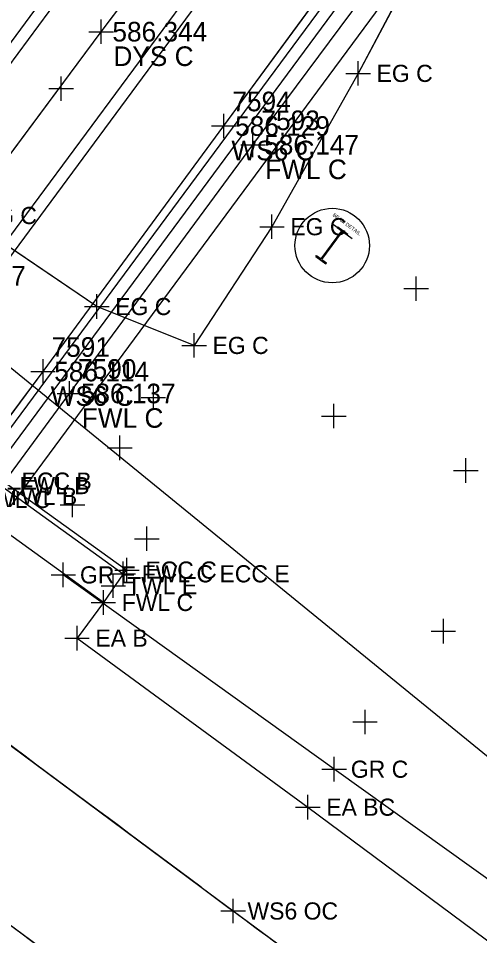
# Model space of a CAD drawing. Extents: x 1324236 to 1326110, y 459090 to 460782.
# Drawn here: x 1325190.8 to 1325228.5, y 460064.8 to 460139.7 of the extents above; entities that cross this region are included whole.
import ezdxf

# ---------------------------------------------------------------- set-up
doc = ezdxf.new("R2010")
doc.units = 0
for name, color, linetype in [('BD_X_Building', 7, 'Continuous'), ('BD_X_Canopy', 7, 'Continuous'), ('DR_X_Ditch', 7, 'Continuous'), ('DR_X_Storm_Sewer', 7, 'Continuous'), ('DT_X_Contour_Text', 7, 'Continuous'), ('DT_X_Terrain_Boundary', 7, 'Continuous'), ('DV_X_Property_Line', 7, 'Continuous'), ('E-RW-ODOT', 7, 'Continuous'), ('LT_X_Poles', 7, 'Continuous'), ('PM_X_Edge_Line', 7, 'Continuous'), ('PM_X_Lane_Line', 7, 'Continuous'), ('PM_X_Misc', 7, 'Continuous'), ('PV_X_Shoulder', 7, 'Continuous'), ('RW_X_CL', 7, 'Continuous'), ('RW_X_Esmt_SH', 7, 'Continuous'), ('UT_X_Gas', 7, 'Continuous')]:
    doc.layers.add(name, color=color, linetype=linetype)

msp = doc.modelspace()

# ---------------------------------------------------------------- linework, layer by layer
at = {"layer": 'BD_X_Building'}
for p, q in [((1325059.964, 459961.355), (1325206.222, 460159.32)), ((1325060.768, 459960.761), (1325207.027, 460158.725)), ((1325067.482, 459955.828), (1325213.75, 460153.784)), ((1325068.286, 459955.234), (1325214.554, 460153.19)), ((1325074.995, 459950.304), (1325221.27, 460148.255)), ((1325075.8, 459949.71), (1325222.074, 460147.66)), ((1325216.852, 460122.579), (1325216.9, 460122.643)), ((1325216.852, 460122.579), (1325217.222, 460122.305)), ((1325216.9, 460122.643), (1325217.704, 460122.049)), ((1325215.535, 460120.021), (1325217.222, 460122.305)), ((1325215.599, 460119.973), (1325217.286, 460122.258)), ((1325217.286, 460122.258), (1325217.656, 460121.984)), ((1325217.656, 460121.984), (1325217.704, 460122.049)), ((1325215.117, 460120.23), (1325215.165, 460120.294)), ((1325215.165, 460120.294), (1325215.535, 460120.021)), ((1325215.117, 460120.23), (1325215.921, 460119.636)), ((1325215.599, 460119.973), (1325215.969, 460119.7)), ((1325215.921, 460119.636), (1325215.969, 460119.7))]:
    msp.add_line(p, q, dxfattribs=at)
msp.add_circle((1325216.443, 460121.116), 3.038, dxfattribs=at)
at = {"layer": 'BD_X_Canopy'}
for points in [[(1325045.611, 459932.876), (1325057.851, 459949.53), (1325064.246, 459958.184), (1325079.335, 459978.633), (1325094.378, 459999.012), (1325110.069, 460020.457), (1325125.333, 460040.949), (1325138.348, 460058.621), (1325153.722, 460079.38), (1325168.359, 460099.091), (1325182.797, 460118.646), (1325197.597, 460138.568), (1325210.747, 460156.012)], [(1325148.737, 460096.817), (1325164.239, 460084.921), (1325164.239, 460084.921), (1325170.939, 460079.893), (1325170.939, 460079.893), (1325200.178, 460058.291), (1325200.178, 460058.291), (1325201.195, 460057.542), (1325201.195, 460057.542), (1325216.328, 460046.448), (1325216.328, 460046.448), (1325227.38, 460038.385), (1325227.38, 460038.385), (1325239.571, 460029.695)]]:
    msp.add_lwpolyline(points, dxfattribs=at)
at = {"layer": 'DR_X_Ditch'}
for points in [[(1325223.493, 460144.483), (1325218.56, 460135.167), (1325211.528, 460122.655), (1325205.182, 460112.968), (1325197.243, 460116.141), (1325186.279, 460123.568), (1325170.666, 460135.994), (1325176.384, 460144.867), (1325182.618, 460152.249), (1325187.649, 460158.581), (1325195.24, 460165.351)], [(1325155.492, 460106.108), (1325171.599, 460094.152), (1325171.599, 460094.152), (1325178.717, 460088.863), (1325178.717, 460088.863), (1325205.765, 460068.751), (1325205.765, 460068.751), (1325208.368, 460066.816), (1325208.368, 460066.816), (1325223.44, 460055.677), (1325223.44, 460055.677), (1325234.507, 460047.596)]]:
    msp.add_lwpolyline(points, dxfattribs=at)
at = {"layer": 'DR_X_Storm_Sewer'}
for p, q in [((1325197.597, 460138.568), (1325210.747, 460156.012)), ((1325182.797, 460118.646), (1325197.597, 460138.568))]:
    msp.add_line(p, q, dxfattribs=at)
at = {"layer": 'DT_X_Contour_Text'}
for p, q in [((1325209.977, 460129.336), (1325223.026, 460146.916)), ((1325223.493, 460144.483), (1325218.56, 460135.167)), ((1325218.56, 460135.167), (1325211.528, 460122.655)), ((1325195.021, 460109.046), (1325209.977, 460129.336)), ((1325197.243, 460116.141), (1325186.279, 460123.568)), ((1325211.528, 460122.655), (1325205.182, 460112.968)), ((1325205.182, 460112.968), (1325197.243, 460116.141)), ((1325180.628, 460089.515), (1325195.021, 460109.046))]:
    msp.add_line(p, q, dxfattribs=at)
at = {"layer": 'DT_X_Terrain_Boundary'}
for p, q in [((1325189.427, 460101.528), (1325199.405, 460094.329)), ((1325197.777, 460091.994), (1325186.129, 460100.396)), ((1325199.405, 460094.329), (1325197.777, 460091.994))]:
    msp.add_line(p, q, dxfattribs=at)
at = {"layer": 'DV_X_Property_Line'}
for p, q in [((1325218.56, 460134.167), (1325218.56, 460136.167)), ((1325217.56, 460135.167), (1325219.56, 460135.167)), ((1325209.977, 460128.336), (1325209.977, 460130.336)), ((1325208.977, 460129.336), (1325210.977, 460129.336)), ((1325211.528, 460121.655), (1325211.528, 460123.655)), ((1325210.528, 460122.655), (1325212.528, 460122.655)), ((1325197.243, 460115.141), (1325197.243, 460117.141)), ((1325196.243, 460116.141), (1325198.243, 460116.141)), ((1325205.182, 460111.968), (1325205.182, 460113.968)), ((1325204.182, 460112.968), (1325206.182, 460112.968)), ((1325195.021, 460108.046), (1325195.021, 460110.046)), ((1325194.021, 460109.046), (1325196.021, 460109.046)), ((1325199.701, 460093.634), (1325199.701, 460095.634)), ((1325199.405, 460093.329), (1325199.405, 460095.329)), ((1325198.405, 460094.329), (1325200.405, 460094.329)), ((1325198.59, 460092.361), (1325198.59, 460094.361)), ((1325198.701, 460094.634), (1325200.701, 460094.634)), ((1325197.59, 460093.361), (1325199.59, 460093.361)), ((1325197.777, 460090.994), (1325197.777, 460092.994)), ((1325196.777, 460091.994), (1325198.777, 460091.994)), ((1325195.63, 460088.08), (1325195.63, 460090.08)), ((1325194.63, 460089.08), (1325196.63, 460089.08)), ((1325214.459, 460074.287), (1325214.459, 460076.287)), ((1325213.459, 460075.287), (1325215.459, 460075.287))]:
    msp.add_line(p, q, dxfattribs=at)
at = {"layer": 'E-RW-ODOT'}
msp.add_line((1325273.546, 460043.161), (1325084.273, 460197.503), dxfattribs=at)
at = {"layer": 'LT_X_Poles'}
msp.add_lwpolyline([(1325155.492, 460106.108), (1325171.599, 460094.152), (1325171.599, 460094.152), (1325178.717, 460088.863), (1325178.717, 460088.863), (1325205.765, 460068.751), (1325205.765, 460068.751), (1325208.368, 460066.816), (1325208.368, 460066.816), (1325223.44, 460055.677), (1325223.44, 460055.677), (1325234.507, 460047.596)], dxfattribs=at)
at = {"layer": 'PM_X_Edge_Line'}
for p, q in [((1325207.605, 460130.872), (1325220.672, 460148.677)), ((1325192.857, 460110.836), (1325207.605, 460130.872)), ((1325178.331, 460091.329), (1325192.857, 460110.836))]:
    msp.add_line(p, q, dxfattribs=at)
msp.add_lwpolyline([(1325043.875, 459908.523), (1325057.387, 459928.027), (1325068.015, 459942.962), (1325074.036, 459951.056), (1325089.476, 459972.013), (1325104.352, 459991.824), (1325119.711, 460012.415), (1325134.634, 460032.509), (1325148.617, 460051.256), (1325163.849, 460071.849), (1325178.331, 460091.329), (1325192.857, 460110.836), (1325207.605, 460130.872), (1325220.672, 460148.677), (1325238.037, 460172.457)], dxfattribs=at)
for centre, radius, start, end in [((917645.083, -88018.408), 683011.891, 53.365301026, 53.368128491), ((1328980.24, 465144.662), 6325.467, 233.3652998, 233.3946818), ((1327520.448, 463179.43), 3877.38, 233.394682, 233.671626)]:
    msp.add_arc(centre, radius, start, end, dxfattribs=at)
at = {"layer": 'PM_X_Lane_Line'}
msp.add_arc((1556801.847, 773572.451), 389782.583, 233.54033854, 233.54568232, dxfattribs=at)
at = {"layer": 'PM_X_Misc'}
for p, q in [((1325216.605, 460078.385), (1325194.512, 460094.242)), ((1325242.925, 460059.5), (1325216.605, 460078.385))]:
    msp.add_line(p, q, dxfattribs=at)
at = {"layer": 'PV_X_Shoulder'}
for points in [[(1325189.608, 460101.894), (1325199.701, 460094.634), (1325199.405, 460094.329)], [(1325197.777, 460091.994), (1325195.63, 460089.08), (1325214.459, 460075.287), (1325231.666, 460062.516), (1325231.666, 460062.516), (1325240.597, 460055.966), (1325240.597, 460055.966), (1325265.143, 460038.106), (1325265.408, 460037.915), (1325265.408, 460037.915), (1325278.984, 460028.122), (1325278.984, 460028.122), (1325292.158, 460018.655), (1325292.158, 460018.655), (1325303.789, 460010.34), (1325303.789, 460010.34), (1325320.262, 459998.574), (1325320.262, 459998.574), (1325335.397, 459987.632), (1325335.397, 459987.632), (1325347.865, 459978.637)]]:
    msp.add_lwpolyline(points, dxfattribs=at)
at = {"layer": 'RW_X_CL'}
for p, q in [((1325197.597, 460137.568), (1325197.597, 460139.568)), ((1325196.597, 460138.568), (1325198.597, 460138.568)), ((1325194.334, 460132.923), (1325194.334, 460134.923)), ((1325193.334, 460133.923), (1325195.334, 460133.923)), ((1325207.605, 460129.872), (1325207.605, 460131.872)), ((1325206.605, 460130.872), (1325208.605, 460130.872)), ((1325223.289, 460116.602), (1325223.289, 460118.602)), ((1325222.289, 460117.602), (1325224.289, 460117.602)), ((1325192.857, 460109.836), (1325192.857, 460111.836)), ((1325191.857, 460110.836), (1325193.857, 460110.836)), ((1325201.855, 460107.725), (1325201.855, 460109.725)), ((1325200.855, 460108.725), (1325202.855, 460108.725)), ((1325216.571, 460106.207), (1325216.571, 460108.207)), ((1325215.571, 460107.207), (1325217.571, 460107.207)), ((1325199.122, 460103.605), (1325199.122, 460105.605)), ((1325198.122, 460104.605), (1325200.122, 460104.605)), ((1325227.338, 460101.765), (1325227.338, 460103.765)), ((1325226.338, 460102.765), (1325228.338, 460102.765)), ((1325195.255, 460098.955), (1325195.255, 460100.955)), ((1325194.255, 460099.955), (1325196.255, 460099.955)), ((1325201.325, 460096.191), (1325201.325, 460098.191)), ((1325200.325, 460097.191), (1325202.325, 460097.191)), ((1325225.506, 460088.648), (1325225.506, 460090.648)), ((1325224.506, 460089.648), (1325226.506, 460089.648)), ((1325219.121, 460081.242), (1325219.121, 460083.242)), ((1325218.121, 460082.242), (1325220.121, 460082.242)), ((1325208.368, 460065.816), (1325208.368, 460067.816)), ((1325207.368, 460066.816), (1325209.368, 460066.816))]:
    msp.add_line(p, q, dxfattribs=at)
at = {"layer": 'RW_X_Esmt_SH'}
for p, q in [((1325194.512, 460093.242), (1325194.512, 460095.242)), ((1325193.512, 460094.242), (1325195.512, 460094.242)), ((1325216.605, 460077.385), (1325216.605, 460079.385)), ((1325215.605, 460078.385), (1325217.605, 460078.385))]:
    msp.add_line(p, q, dxfattribs=at)
at = {"layer": 'UT_X_Gas'}
for p, q in [((1325078.063, 459948.049), (1325224.327, 460146.007)), ((1325216.852, 460122.579), (1325216.45, 460122.876)), ((1325217.656, 460121.984), (1325218.059, 460121.687))]:
    msp.add_line(p, q, dxfattribs=at)

# ---------------------------------------------------------------- texts
at = {"layer": 'BD_X_Building'}
msp.add_text('BEAM DETAIL', height=0.3, rotation=323.5441, dxfattribs=at).set_placement((1325216.447, 460123.55))
at = {"layer": 'DV_X_Property_Line'}
for s, height, p in [('EG C', 1.4, (1325220.06, 460134.467)), ('7593', 1.6, (1325210.672, 460130.536)), ('586.147', 1.6, (1325210.895, 460128.536)), ('FWL C', 1.6, (1325210.977, 460126.536)), ('EG C', 1.4, (1325187.779, 460122.868)), ('EG C', 1.4, (1325213.028, 460121.955)), ('EG C', 1.4, (1325198.743, 460115.441)), ('EG C', 1.4, (1325206.682, 460112.268)), ('7590', 1.6, (1325195.716, 460110.246)), ('586.137', 1.6, (1325195.939, 460108.246)), ('FWL C', 1.6, (1325196.021, 460106.246)), ('ECC B', 1.4, (1325191.108, 460101.194)), ('FWL B', 1.4, (1325190.927, 460100.828)), ('FWL C', 1.4, (1325187.629, 460099.695)), ('TWL B', 1.4, (1325189.921, 460099.952)), ('FWL C ECC E', 1.4, (1325200.905, 460093.629)), ('ECC C', 1.4, (1325201.201, 460093.934)), ('TWL E', 1.4, (1325199.715, 460092.661)), ('FWL C', 1.4, (1325199.277, 460091.294)), ('EA B', 1.4, (1325197.13, 460088.38)), ('EA BC', 1.4, (1325215.959, 460074.587))]:
    msp.add_text(s, height=height, dxfattribs=at).set_placement(p)
at = {"layer": 'RW_X_CL'}
for s, height, p in [('586.344', 1.6, (1325198.515, 460137.768)), ('DYS C', 1.6, (1325198.597, 460135.768)), ('7594', 1.6, (1325208.3, 460132.072)), ('586.129', 1.6, (1325208.523, 460130.072)), ('WS6 C', 1.6, (1325208.224, 460128.072)), ('586.327', 1.6, (1325183.715, 460117.846)), ('7591', 1.6, (1325193.552, 460112.036)), ('586.114', 1.6, (1325193.775, 460110.036)), ('WS6 C', 1.6, (1325193.476, 460108.036)), ('WS6 OC', 1.4, (1325209.535, 460066.116))]:
    msp.add_text(s, height=height, dxfattribs=at).set_placement(p)
at = {"layer": 'RW_X_Esmt_SH'}
for s, p in [('GR E', (1325195.869, 460093.542)), ('GR C', (1325217.962, 460077.685))]:
    msp.add_text(s, height=1.4, dxfattribs=at).set_placement(p)

doc.saveas('drawing.dxf')
